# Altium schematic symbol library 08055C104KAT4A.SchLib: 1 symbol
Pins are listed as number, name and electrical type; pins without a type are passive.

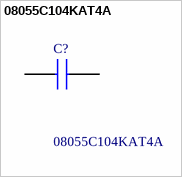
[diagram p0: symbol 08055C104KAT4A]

## 08055C104KAT4A
designator C?
AVX, 0805 (2012M) 100nF MLCC 50V dc +/-10% , SMD 08055C104KAT4A; Manufacturer_Name: Kyocera AVX; Geometry.Height: 0.94mm
footprint CAPC2012X94N
pins: 1, 2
